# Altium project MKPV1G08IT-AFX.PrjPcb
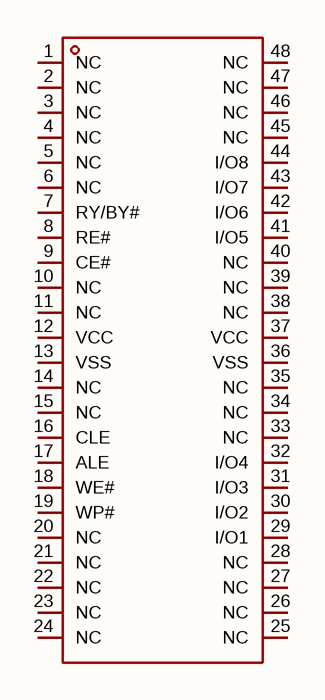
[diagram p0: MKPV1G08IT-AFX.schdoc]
1 sheet, 1 parts. Net scope: global (net labels, ports and power ports of the same name join across sheets).

## Sheet MKPV1G08IT-AFX.schdoc
size 127 x 101 mm

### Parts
U?  mkpv1g08it-afx  [TSOP-48_L12.0-W18.4-P0.50-LS20.0-BL]  (value not drawn)

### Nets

Not connected (* = marked no-connect by the designer): U? 1(NC) 2(NC) 3(NC) 4(NC) 5(NC) 6(NC) 7(RY/BY#) 8(RE#) 9(CE#) 10(NC) 11(NC) 12(VCC) 13(VSS) 14(NC) 15(NC) 16(CLE) 17(ALE) 18(WE#) 19(WP#) 20(NC) 21(NC) 22(NC) 23(NC) 24(NC) 25(NC) 26(NC) 27(NC) 28(NC) 29(I/O1) 30(I/O2) 31(I/O3) 32(I/O4) 33(NC) 34(NC) 35(NC) 36(VSS) 37(VCC) 38(NC) 39(NC) 40(NC) 41(I/O5) 42(I/O6) 43(I/O7) 44(I/O8) 45(NC) 46(NC) 47(NC) 48(NC)

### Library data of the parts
U? = mkpv1g08it-afx: 存储容量:1Gbit;时钟频率(fc):40MHz;工作电压:2.7V~3.6V;; Manufacturer: MK(米客方德); AddInBom: yes; ModelId: 84317263936c4cfc959f23406aa8adae; ModelName: TSOP-48_L12-W18.4-H1.0-LS20.0-P0.50; ModelTransform: 788.19,472.441,0,90,0,0,0,0,0; Memory Size: 1Gbit; Clock Frequency: 40MHz; Write Cycle Time(tWC): 25ns; Page Program time (TPP): 300us; Block Erase Time(tBE): 2.5ms; Standby Supply Current: 50uA; ECC: 有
